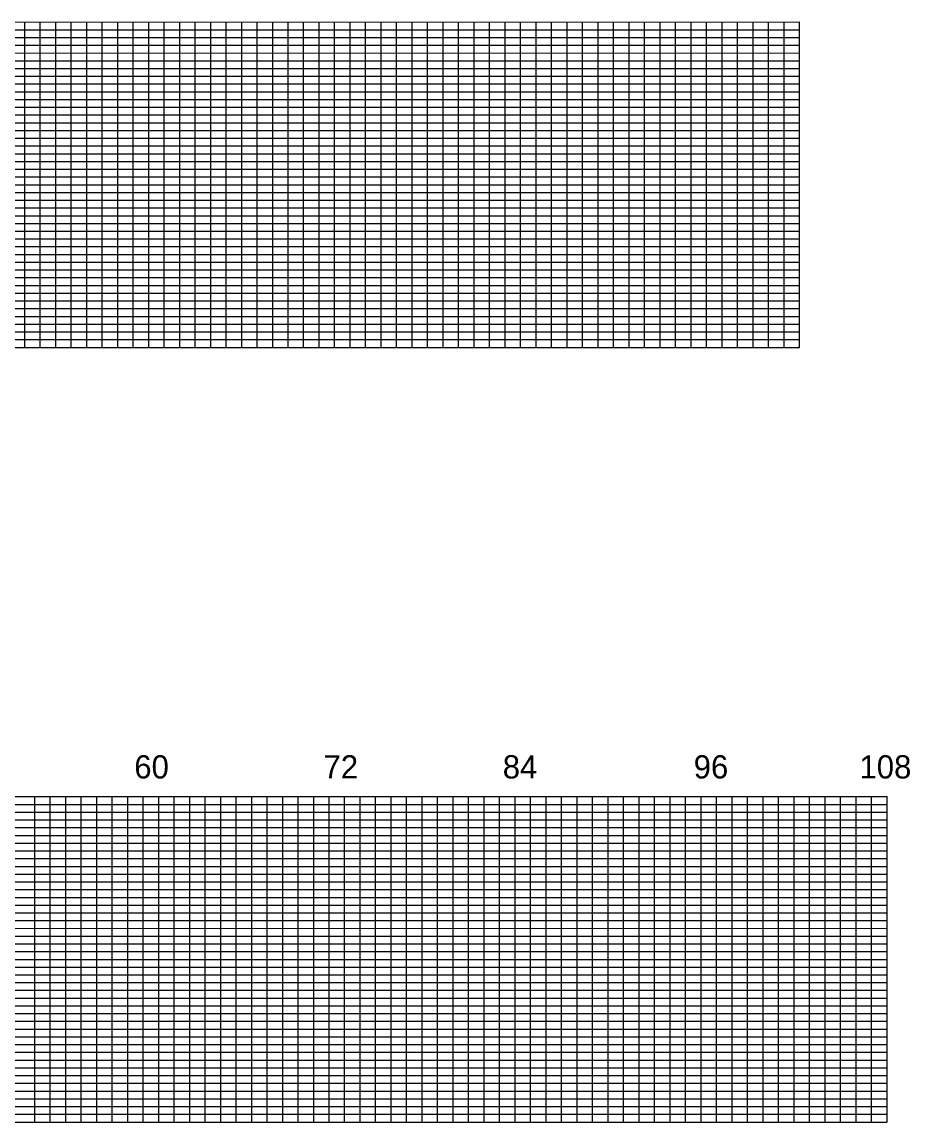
# Model space of a CAD drawing. Extents: x 1914168 to 1925341, y 720939 to 777401.
# Drawn here: x 1917044 to 1919910, y 763464 to 767014 of the extents above; entities that cross this region are included whole.
import ezdxf

# ---------------------------------------------------------------- set-up
doc = ezdxf.new("R2010")
doc.units = 0
doc.layers.add('RD_PD_WallFill', color=7, linetype='Continuous')

msp = doc.modelspace()

# ---------------------------------------------------------------- linework, layer by layer
at = {"layer": 'RD_PD_WallFill'}
for p, q in [((1914203.2, 767014.1), (1919553.2, 767014.2)), ((1914653.2, 766989.1), (1919553.2, 766989.1)), ((1917053.2, 765964.2), (1917053.2, 767014.2)), ((1917103.2, 765964.2), (1917103.2, 767014.2)), ((1917153.2, 765964.2), (1917153.2, 767014.2)), ((1917203.2, 765964.2), (1917203.2, 767014.2)), ((1917253.2, 765964.2), (1917253.2, 767014.2)), ((1917303.2, 765964.1), (1917303.2, 767014.2)), ((1917353.2, 765964.2), (1917353.2, 767014.2)), ((1917403.2, 765964.2), (1917403.2, 767014.2)), ((1917453.2, 765964.2), (1917453.2, 767014.2)), ((1917503.2, 765964.2), (1917503.2, 767014.2)), ((1917553.2, 765964.2), (1917553.2, 767014.2)), ((1917603.2, 765964.1), (1917603.2, 767014.2)), ((1917653.2, 765964.1), (1917653.2, 767014.2)), ((1917703.2, 765964.2), (1917703.2, 767014.2)), ((1917753.2, 765964.2), (1917753.2, 767014.2)), ((1917803.2, 765964.2), (1917803.2, 767014.2)), ((1917853.2, 765964.2), (1917853.2, 767014.2)), ((1917903.2, 765964.2), (1917903.2, 767014.2)), ((1917953.2, 765964.2), (1917953.2, 767014.2)), ((1918003.2, 765964.2), (1918003.2, 767014.2)), ((1918053.2, 765964.2), (1918053.2, 767014.2)), ((1918103.2, 765964.2), (1918103.2, 767014.2)), ((1918153.2, 765964.2), (1918153.2, 767014.2)), ((1918203.2, 765964.2), (1918203.2, 767014.2)), ((1918253.2, 765964.2), (1918253.2, 767014.2)), ((1918303.2, 765964.2), (1918303.2, 767014.2)), ((1918353.2, 765964.2), (1918353.2, 767014.2)), ((1918403.2, 765964.2), (1918403.2, 767014.2)), ((1918453.2, 765964.2), (1918453.2, 767014.2)), ((1918503.2, 765964.2), (1918503.2, 767014.2)), ((1918553.2, 765964.2), (1918553.2, 767014.2)), ((1918603.2, 765964.2), (1918603.2, 767014.2)), ((1918653.2, 765964.2), (1918653.2, 767014.2)), ((1918703.2, 765964.2), (1918703.2, 767014.2)), ((1918753.2, 765964.2), (1918753.2, 767014.2)), ((1918803.2, 765964.2), (1918803.2, 767014.2)), ((1918853.2, 765964.2), (1918853.2, 767014.2)), ((1918903.2, 765964.2), (1918903.2, 767014.2)), ((1918953.2, 765964.2), (1918953.2, 767014.2)), ((1919003.2, 765964.2), (1919003.2, 767014.2)), ((1919053.2, 765964.2), (1919053.2, 767014.2)), ((1919103.2, 765964.2), (1919103.2, 767014.2)), ((1919153.2, 765964.2), (1919153.2, 767014.2)), ((1919203.2, 765964.2), (1919203.2, 767014.2)), ((1919253.2, 765964.2), (1919253.2, 767014.2)), ((1919303.2, 765964.2), (1919303.2, 767014.2)), ((1919353.2, 765964.2), (1919353.2, 767014.2)), ((1919403.2, 765964.2), (1919403.2, 767014.2)), ((1919453.2, 765964.2), (1919453.2, 767014.2)), ((1919503.2, 765964.2), (1919503.2, 767014.2)), ((1919553.2, 765964.2), (1919553.2, 767014.2)), ((1914653.2, 766964.1), (1919553.2, 766964.1)), ((1914653.2, 766939.1), (1919553.2, 766939.1)), ((1914653.2, 766914.2), (1919553.2, 766914.1)), ((1914653.2, 766889.1), (1919553.2, 766889.2)), ((1914203.2, 766864.1), (1919553.2, 766864.1)), ((1914203.2, 766839.1), (1919553.2, 766839.1)), ((1914203.2, 766814.1), (1919553.2, 766814.2)), ((1914203.2, 766789.2), (1919553.2, 766789.1)), ((1914203.2, 766764.2), (1919553.2, 766764.2)), ((1914203.2, 766739.1), (1919553.2, 766739.1)), ((1914203.2, 766714.1), (1919553.2, 766714.1)), ((1914203.2, 766689.2), (1919553.2, 766689.1)), ((1914203.2, 766664.1), (1919553.2, 766664.1)), ((1914203.2, 766639.2), (1919553.2, 766639.1)), ((1914203.2, 766614.1), (1919553.2, 766614.1)), ((1914203.2, 766589.1), (1919553.2, 766589.2)), ((1914203.2, 766564.1), (1919553.2, 766564.1)), ((1914203.2, 766539.1), (1919553.2, 766539.2)), ((1914203.2, 766514.1), (1919553.2, 766514.1)), ((1914203.2, 766489.1), (1919553.2, 766489.1)), ((1914203.2, 766464.2), (1919553.2, 766464.1)), ((1914203.2, 766439.1), (1919553.2, 766439.1)), ((1914203.2, 766414.1), (1919553.2, 766414.1)), ((1914203.2, 766389.1), (1919553.2, 766389.1)), ((1914203.2, 766364.1), (1919553.2, 766364.2)), ((1914203.2, 766339.1), (1919553.2, 766339.1)), ((1914203.2, 766314.1), (1919553.2, 766314.1)), ((1914203.2, 766289.1), (1919553.2, 766289.1)), ((1914203.2, 766264.1), (1919553.2, 766264.1)), ((1914203.2, 766239.1), (1919553.2, 766239.1)), ((1914203.2, 766214.1), (1919553.2, 766214.1)), ((1914203.2, 766189.1), (1919553.2, 766189.1)), ((1914203.2, 766164.1), (1919553.2, 766164.1)), ((1914203.2, 766139.1), (1919553.2, 766139.1)), ((1914203.2, 766114.1), (1919553.2, 766114.1)), ((1914203.2, 766089.1), (1919553.2, 766089.1)), ((1914203.2, 766064.1), (1919553.2, 766064.1)), ((1914203.2, 766039.1), (1919553.2, 766039.1)), ((1914203.2, 766014.1), (1919553.2, 766014.1)), ((1914253.2, 765989.1), (1919553.2, 765989.1)), ((1914203.2, 765964.1), (1919553.2, 765964.1)), ((1914485.5, 764514.1), (1919835.5, 764514.2)), ((1917085.5, 763464.2), (1917085.5, 764514.2)), ((1917135.5, 763464.2), (1917135.5, 764514.2)), ((1917185.5, 763464.2), (1917185.5, 764514.2)), ((1917235.5, 763464.2), (1917235.5, 764514.2)), ((1917285.5, 763464.2), (1917285.5, 764514.2)), ((1917335.5, 763464.2), (1917335.5, 764514.2)), ((1917385.5, 763464.2), (1917385.5, 764514.2)), ((1917435.5, 763464.2), (1917435.5, 764514.2)), ((1917485.5, 763464.2), (1917485.5, 764514.2)), ((1917535.5, 763464.2), (1917535.5, 764514.2)), ((1917585.5, 763464.1), (1917585.5, 764514.2)), ((1917635.5, 763464.2), (1917635.5, 764514.2)), ((1917685.5, 763464.2), (1917685.5, 764514.2)), ((1917735.5, 763464.2), (1917735.5, 764514.2)), ((1917785.5, 763464.2), (1917785.5, 764514.2)), ((1917835.5, 763464.2), (1917835.5, 764514.2)), ((1917885.5, 763464.1), (1917885.5, 764514.2)), ((1917935.5, 763464.1), (1917935.5, 764514.2)), ((1917985.5, 763464.2), (1917985.5, 764514.2)), ((1918035.5, 763464.2), (1918035.5, 764514.2)), ((1918085.5, 763464.2), (1918085.5, 764514.2)), ((1918135.5, 763464.2), (1918135.5, 764514.2)), ((1918185.5, 763464.2), (1918185.5, 764514.2)), ((1918235.5, 763464.2), (1918235.5, 764514.2)), ((1918285.5, 763464.2), (1918285.5, 764514.2)), ((1918335.5, 763464.2), (1918335.5, 764514.2)), ((1918385.5, 763464.2), (1918385.5, 764514.2)), ((1918435.5, 763464.2), (1918435.5, 764514.2)), ((1918485.5, 763464.2), (1918485.5, 764514.2)), ((1918535.5, 763464.2), (1918535.5, 764514.2)), ((1918585.5, 763464.2), (1918585.5, 764514.2)), ((1918635.5, 763464.2), (1918635.5, 764514.2)), ((1918685.5, 763464.2), (1918685.5, 764514.2)), ((1918735.5, 763464.2), (1918735.5, 764514.2)), ((1918785.5, 763464.2), (1918785.5, 764514.2)), ((1918835.5, 763464.2), (1918835.5, 764514.2)), ((1918885.5, 763464.2), (1918885.5, 764514.2)), ((1918935.5, 763464.2), (1918935.5, 764514.2)), ((1918985.5, 763464.2), (1918985.5, 764514.2)), ((1919035.5, 763464.2), (1919035.5, 764514.2)), ((1919085.5, 763464.2), (1919085.5, 764514.2)), ((1919135.5, 763464.2), (1919135.5, 764514.2)), ((1919185.5, 763464.2), (1919185.5, 764514.2)), ((1919235.5, 763464.2), (1919235.5, 764514.2)), ((1919285.5, 763464.2), (1919285.5, 764514.2)), ((1919335.5, 763464.2), (1919335.5, 764514.2)), ((1919385.5, 763464.2), (1919385.5, 764514.2)), ((1919435.5, 763464.2), (1919435.5, 764514.2)), ((1919485.5, 763464.2), (1919485.5, 764514.2)), ((1919535.5, 763464.2), (1919535.5, 764514.2)), ((1919585.5, 763464.2), (1919585.5, 764514.2)), ((1919635.5, 763464.2), (1919635.5, 764514.2)), ((1919685.5, 763464.2), (1919685.5, 764514.2)), ((1919735.5, 763464.2), (1919735.5, 764514.2)), ((1919785.5, 763464.2), (1919785.5, 764514.2)), ((1919835.5, 763464.2), (1919835.5, 764514.2)), ((1914935.5, 764489.1), (1919835.5, 764489.1)), ((1914935.5, 764464.1), (1919835.5, 764464.1)), ((1914935.5, 764439.1), (1919835.5, 764439.1)), ((1914935.5, 764414.2), (1919835.5, 764414.1)), ((1914935.5, 764389.1), (1919835.5, 764389.2)), ((1914485.5, 764364.1), (1919835.5, 764364.1)), ((1914485.5, 764339.1), (1919835.5, 764339.1)), ((1914485.5, 764314.1), (1919835.5, 764314.2)), ((1914485.5, 764289.2), (1919835.5, 764289.1)), ((1914485.5, 764264.2), (1919835.5, 764264.2)), ((1914485.5, 764239.1), (1919835.5, 764239.1)), ((1914485.5, 764214.1), (1919835.5, 764214.1)), ((1914485.5, 764189.2), (1919835.5, 764189.1)), ((1914485.5, 764164.1), (1919835.5, 764164.1)), ((1914485.5, 764139.2), (1919835.5, 764139.1)), ((1914485.5, 764114.1), (1919835.5, 764114.1)), ((1914485.5, 764089.1), (1919835.5, 764089.2)), ((1914485.5, 764064.1), (1919835.5, 764064.1)), ((1914485.5, 764039.1), (1919835.5, 764039.2)), ((1914485.5, 764014.1), (1919835.5, 764014.1)), ((1914485.5, 763989.1), (1919835.5, 763989.1)), ((1914485.5, 763964.2), (1919835.5, 763964.1)), ((1914485.5, 763939.1), (1919835.5, 763939.1)), ((1914485.5, 763914.1), (1919835.5, 763914.1)), ((1914485.5, 763889.1), (1919835.5, 763889.1)), ((1914485.5, 763864.1), (1919835.5, 763864.2)), ((1914485.5, 763839.1), (1919835.5, 763839.1)), ((1914485.5, 763814.1), (1919835.5, 763814.1)), ((1914485.5, 763789.1), (1919835.5, 763789.1)), ((1914485.5, 763764.1), (1919835.5, 763764.1)), ((1914485.5, 763739.1), (1919835.5, 763739.1)), ((1914485.5, 763714.1), (1919835.5, 763714.1)), ((1914485.5, 763689.1), (1919835.5, 763689.1)), ((1914485.5, 763664.1), (1919835.5, 763664.1)), ((1914485.5, 763639.1), (1919835.5, 763639.1)), ((1914485.5, 763614.1), (1919835.5, 763614.1)), ((1914485.5, 763589.1), (1919835.5, 763589.1)), ((1914485.5, 763564.1), (1919835.5, 763564.1)), ((1914485.5, 763539.1), (1919835.5, 763539.1)), ((1914485.5, 763514.1), (1919835.5, 763514.1)), ((1914535.5, 763489.1), (1919835.5, 763489.1)), ((1914485.5, 763464.1), (1919835.5, 763464.1))]:
    msp.add_line(p, q, dxfattribs=at)

# ---------------------------------------------------------------- texts
for s, p in [('60', (1917406.7, 764572.8)), ('72', (1918017.3, 764572.8)), ('84', (1918595.6, 764572.8)), ('96', (1919211.7, 764572.8)), ('108', (1919746.7, 764572.8))]:
    msp.add_text(s, height=75, dxfattribs=at).set_placement(p)

doc.saveas('drawing.dxf')
